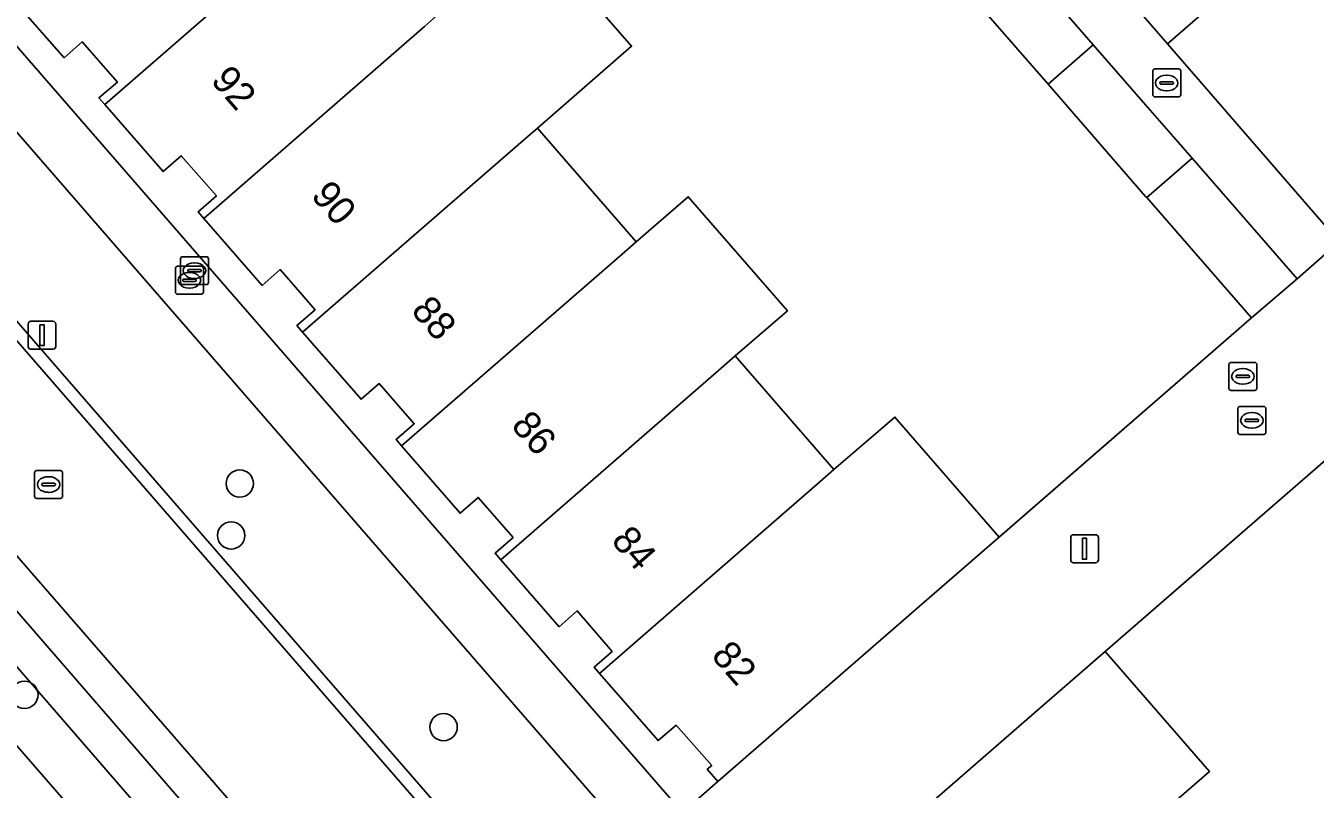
# Model space of a CAD drawing. Extents: x 155887 to 156869, y 383880 to 384678.
# Drawn here: x 156459.92 to 156506.07, y 384116.44 to 384143.78 of the extents above; entities that cross this region are included whole.
import ezdxf

# ---------------------------------------------------------------- set-up
doc = ezdxf.new("R2010")
doc.units = 0
for name, color, linetype in [('IMGEO_Berm_groen', 7, 'Continuous'), ('IMGEO_Boom', 7, 'Continuous'), ('IMGEO_Brandkraan', 7, 'Continuous'), ('IMGEO_Erf', 7, 'Continuous'), ('IMGEO_Greppel_droge_sloot', 7, 'Continuous'), ('IMGEO_Kolk', 7, 'Continuous'), ('IMGEO_Lichtmast', 7, 'Continuous'), ('IMGEO_Muur', 7, 'Continuous'), ('IMGEO_OVBaan_gesloten', 7, 'Continuous'), ('IMGEO_Pand', 7, 'Continuous'), ('IMGEO_Pand_nummerreeks', 7, 'Continuous'), ('IMGEO_Parkeervlak_open', 7, 'Continuous'), ('IMGEO_Rijbaan_lokaal_gesloten', 7, 'Continuous'), ('IMGEO_Rijbaan_lokaal_open', 7, 'Continuous'), ('IMGEO_Rioolput', 7, 'Continuous'), ('IMGEO_Voetpad_open', 7, 'Continuous')]:
    doc.layers.add(name, color=color, linetype=linetype)

msp = doc.modelspace()

# ---------------------------------------------------------------- linework, layer by layer
at = {"layer": 'IMGEO_Berm_groen'}
for points in [[(156520.535, 384054.614), (156504.298, 384073.374), (156500, 384078.319), (156478.069, 384103.539), (156435.386, 384152.651), (156395.779, 384198.307), (156392.544, 384201.972), (156392.213, 384201.678), (156391.898, 384201.399), (156389.213, 384199.015), (156500, 384071.498), (156517.145, 384051.764)], [(156518.628, 384053.007), (156500, 384074.342), (156481.572, 384095.447), (156445.697, 384136.86), (156396.295, 384193.376), (156399.832, 384191.076), (156406.998, 384183.444), (156446.804, 384137.574), (156482.527, 384096.349), (156500, 384076.291), (156519.582, 384053.811)]]:
    msp.add_lwpolyline(points, dxfattribs=at)
at = {"layer": 'IMGEO_Boom'}
for centre in [(156467.574, 384127.385), (156467.265, 384125.531), (156459.865, 384119.824), (156474.872, 384118.668)]:
    msp.add_circle(centre, 0.489, dxfattribs=at)
at = {"layer": 'IMGEO_Brandkraan'}
for p, q in [((156465.454, 384134.583), (156465.454, 384135.435)), ((156465.529, 384135.509), (156466.381, 384135.509)), ((156465.942, 384135.289), (156465.967, 384135.289)), ((156466.455, 384135.435), (156466.455, 384134.583)), ((156465.274, 384134.239), (156465.274, 384135.091)), ((156465.349, 384135.165), (156466.201, 384135.165)), ((156465.713, 384135.003), (156465.713, 384135.015)), ((156466.151, 384134.966), (156465.753, 384134.966)), ((156465.756, 384135.052), (156466.154, 384135.052)), ((156465.762, 384134.945), (156465.787, 384134.945)), ((156466.197, 384135.015), (156466.197, 384135.003)), ((156466.275, 384135.091), (156466.275, 384134.239)), ((156466.381, 384134.509), (156465.529, 384134.509)), ((156465.533, 384134.659), (156465.533, 384134.671)), ((156465.971, 384134.622), (156465.573, 384134.622)), ((156465.576, 384134.708), (156465.974, 384134.708)), ((156465.785, 384134.385), (156465.76, 384134.385)), ((156465.965, 384134.729), (156465.94, 384134.729)), ((156466.017, 384134.671), (156466.017, 384134.659)), ((156466.201, 384134.165), (156465.349, 384134.165))]:
    msp.add_line(p, q, dxfattribs=at)
for points in [[(156465.454, 384134.583), (156465.454, 384135.435)], [(156465.529, 384135.509), (156466.381, 384135.509)], [(156466.455, 384135.435), (156466.455, 384134.583)], [(156465.274, 384134.239), (156465.274, 384135.091)], [(156465.349, 384135.165), (156466.201, 384135.165)], [(156466.275, 384135.091), (156466.275, 384134.239)], [(156466.381, 384134.509), (156465.529, 384134.509)], [(156466.201, 384134.165), (156465.349, 384134.165)]]:
    msp.add_lwpolyline(points, dxfattribs=at)
for centre, radius, start, end in [((156465.531, 384135.433), 0.0765, 91.552, 178.448), ((156465.531, 384135.433), 0.0765, 91.552, 178.448), ((156466.379, 384135.433), 0.0765, 1.552, 88.448), ((156466.379, 384135.433), 0.0765, 1.552, 88.448), ((156465.351, 384135.089), 0.0765, 91.552, 178.448), ((156465.351, 384135.089), 0.0765, 91.552, 178.448), ((156465.753, 384135.012), 0.0403, 85.8775, 175.7526), ((156465.75, 384135.002), 0.0366, 178.938, 274.7102), ((156466.154, 384135.009), 0.043, 264.8664, 352.4533), ((156466.158, 384135.014), 0.0386, 1.7309, 96.639), ((156466.199, 384135.089), 0.0765, 1.552, 88.448), ((156466.199, 384135.089), 0.0765, 1.552, 88.448), ((156465.531, 384134.585), 0.0765, 181.552, 268.448), ((156465.531, 384134.585), 0.0765, 181.552, 268.448), ((156465.573, 384134.668), 0.0403, 85.8775, 175.7526), ((156465.57, 384134.658), 0.0366, 178.938, 274.7102), ((156465.974, 384134.665), 0.043, 264.8664, 352.4533), ((156465.978, 384134.67), 0.0386, 1.7309, 96.639), ((156466.379, 384134.585), 0.0765, 271.552, 358.448), ((156466.379, 384134.585), 0.0765, 271.552, 358.448), ((156465.351, 384134.241), 0.0765, 181.552, 268.448), ((156465.351, 384134.241), 0.0765, 181.552, 268.448), ((156466.199, 384134.241), 0.0765, 271.552, 358.448), ((156466.199, 384134.241), 0.0765, 271.552, 358.448)]:
    msp.add_arc(centre, radius, start, end, dxfattribs=at)
for centre, major_axis, ratio, start_param, end_param in [((156465.941, 384135.009), (-0.387, 0.002), 0.722429, 4.712389, 7.853982), ((156465.966, 384135.009), (-0.39, 0.002), 0.717154, 1.570796, 4.712389), ((156465.761, 384134.665), (-0.387, 0.002), 0.722429, 4.712389, 7.853982), ((156465.786, 384134.665), (-0.39, 0.002), 0.717154, 1.570796, 4.712389)]:
    msp.add_ellipse(centre, major_axis=major_axis, ratio=ratio, start_param=start_param, end_param=end_param, dxfattribs=at)
at = {"layer": 'IMGEO_Erf'}
for points in [[(156447.623, 384156.834), (156483.427, 384115.614), (156484.683, 384116.72), (156484.308, 384117.159), (156484.468, 384117.295), (156483.201, 384118.73), (156482.547, 384118.183), (156480.45, 384120.589), (156480.257, 384120.81), (156480.906, 384121.375), (156479.656, 384122.826), (156479.008, 384122.26), (156476.917, 384124.656), (156476.713, 384124.89), (156477.361, 384125.456), (156476.11, 384126.89), (156475.461, 384126.326), (156473.369, 384128.736), (156473.17, 384128.966), (156473.819, 384129.53), (156472.567, 384130.968), (156471.918, 384130.403), (156469.826, 384132.807), (156469.621, 384133.043), (156470.27, 384133.607), (156469.025, 384135.047), (156468.377, 384134.482), (156466.286, 384136.882), (156466.083, 384137.115), (156466.738, 384137.686), (156465.481, 384139.124), (156464.833, 384138.559), (156462.744, 384140.954), (156462.534, 384141.194), (156463.199, 384141.759), (156461.94, 384143.198), (156461.292, 384142.633), (156459.196, 384145.034)], [(156478.058, 384147.119), (156481.599, 384143.047), (156478.23, 384140.116), (156481.768, 384136.039), (156483.627, 384137.657), (156487.176, 384133.576), (156485.312, 384131.955), (156488.844, 384127.885), (156490.676, 384129.465), (156491.026, 384129.767), (156494.76, 384125.465), (156503.787, 384133.316), (156500.039, 384137.624), (156500, 384137.669), (156496.505, 384141.686), (156492.954, 384145.767)], [(156500, 384144.033), (156500.779, 384143.137), (156504.594, 384146.446)], [(156507.439, 384129.09), (156498.546, 384121.378), (156502.29, 384117.077), (156499.486, 384114.64), (156500, 384114.048), (156503.026, 384110.564), (156506.565, 384106.489)]]:
    msp.add_lwpolyline(points, dxfattribs=at)
at = {"layer": 'IMGEO_Greppel_droge_sloot'}
msp.add_lwpolyline([(156519.582, 384053.811), (156500, 384076.291), (156482.527, 384096.349), (156446.804, 384137.574), (156406.998, 384183.444), (156399.832, 384191.076), (156396.295, 384193.376), (156445.697, 384136.86), (156481.572, 384095.447), (156500, 384074.342), (156518.628, 384053.007)], close=True, dxfattribs=at)
at = {"layer": 'IMGEO_Kolk'}
for p, q in [((156500.253, 384141.304), (156500.253, 384142.156)), ((156500.328, 384142.23), (156501.18, 384142.23)), ((156501.254, 384142.156), (156501.254, 384141.304)), ((156500.512, 384141.724), (156500.512, 384141.736)), ((156500.95, 384141.687), (156500.552, 384141.687)), ((156500.555, 384141.773), (156500.953, 384141.773)), ((156500.741, 384142.01), (156500.766, 384142.01)), ((156500.996, 384141.736), (156500.996, 384141.724)), ((156501.18, 384141.23), (156500.328, 384141.23)), ((156500.764, 384141.45), (156500.739, 384141.45)), ((156503.376, 384130.148), (156504.228, 384130.148)), ((156503.301, 384129.222), (156503.301, 384130.074)), ((156503.603, 384129.691), (156504.001, 384129.691)), ((156503.789, 384129.928), (156503.814, 384129.928)), ((156504.302, 384130.074), (156504.302, 384129.222)), ((156503.56, 384129.642), (156503.56, 384129.654)), ((156503.998, 384129.605), (156503.6, 384129.605)), ((156503.812, 384129.368), (156503.787, 384129.368)), ((156504.044, 384129.654), (156504.044, 384129.642)), ((156504.228, 384129.148), (156503.376, 384129.148))]:
    msp.add_line(p, q, dxfattribs=at)
for points in [[(156500.253, 384141.304), (156500.253, 384142.156)], [(156500.328, 384142.23), (156501.18, 384142.23)], [(156501.254, 384142.156), (156501.254, 384141.304)], [(156501.18, 384141.23), (156500.328, 384141.23)], [(156503.376, 384130.148), (156504.228, 384130.148)], [(156503.301, 384129.222), (156503.301, 384130.074)], [(156504.302, 384130.074), (156504.302, 384129.222)], [(156504.228, 384129.148), (156503.376, 384129.148)]]:
    msp.add_lwpolyline(points, dxfattribs=at)
for centre, radius, start, end in [((156500.33, 384142.154), 0.0765, 91.552, 178.448), ((156500.33, 384142.154), 0.0765, 91.552, 178.448), ((156501.178, 384142.154), 0.0765, 1.552, 88.448), ((156501.178, 384142.154), 0.0765, 1.552, 88.448), ((156500.552, 384141.733), 0.0403, 85.8775, 175.7526), ((156500.549, 384141.723), 0.0366, 178.938, 274.7102), ((156500.953, 384141.73), 0.043, 264.8664, 352.4533), ((156500.957, 384141.735), 0.0386, 1.7309, 96.639), ((156500.33, 384141.306), 0.0765, 181.552, 268.448), ((156500.33, 384141.306), 0.0765, 181.552, 268.448), ((156501.178, 384141.306), 0.0765, 271.552, 358.448), ((156501.178, 384141.306), 0.0765, 271.552, 358.448), ((156503.378, 384130.072), 0.0765, 91.552, 178.448), ((156503.378, 384130.072), 0.0765, 91.552, 178.448), ((156504.226, 384130.072), 0.0765, 1.552, 88.448), ((156504.226, 384130.072), 0.0765, 1.552, 88.448), ((156503.6, 384129.651), 0.0403, 85.8775, 175.7526), ((156504.005, 384129.653), 0.0386, 1.7309, 96.639), ((156503.378, 384129.224), 0.0765, 181.552, 268.448), ((156503.378, 384129.224), 0.0765, 181.552, 268.448), ((156503.597, 384129.641), 0.0366, 178.938, 274.7102), ((156504.001, 384129.648), 0.043, 264.8664, 352.4533), ((156504.226, 384129.224), 0.0765, 271.552, 358.448), ((156504.226, 384129.224), 0.0765, 271.552, 358.448)]:
    msp.add_arc(centre, radius, start, end, dxfattribs=at)
for centre, major_axis, ratio, start_param, end_param in [((156500.74, 384141.73), (-0.387, 0.002), 0.722429, 4.712389, 7.853982), ((156500.765, 384141.73), (-0.39, 0.002), 0.717154, 1.570796, 4.712389), ((156503.788, 384129.648), (-0.387, 0.002), 0.722429, 4.712389, 7.853982), ((156503.813, 384129.648), (-0.39, 0.002), 0.717154, 1.570796, 4.712389)]:
    msp.add_ellipse(centre, major_axis=major_axis, ratio=ratio, start_param=start_param, end_param=end_param, dxfattribs=at)
at = {"layer": 'IMGEO_Lichtmast'}
for p, q in [((156460, 384132.299), (156460, 384133.099)), ((156460, 384133.099), (156460, 384132.299)), ((156460.1, 384133.199), (156460.89, 384133.199)), ((156460.89, 384133.199), (156460.1, 384133.199)), ((156460.99, 384133.099), (156460.99, 384132.299)), ((156460.99, 384132.299), (156460.99, 384133.099)), ((156460.89, 384132.199), (156460.1, 384132.199)), ((156460.1, 384132.199), (156460.89, 384132.199)), ((156497.418, 384125.553), (156498.208, 384125.553)), ((156498.208, 384125.553), (156497.418, 384125.553)), ((156497.318, 384124.653), (156497.318, 384125.453)), ((156497.318, 384125.453), (156497.318, 384124.653)), ((156498.308, 384125.453), (156498.308, 384124.653)), ((156498.308, 384124.653), (156498.308, 384125.453)), ((156498.208, 384124.553), (156497.418, 384124.553)), ((156497.418, 384124.553), (156498.208, 384124.553))]:
    msp.add_line(p, q, dxfattribs=at)
for points in [[(156460.42, 384133.074), (156460.57, 384133.074), (156460.57, 384132.324), (156460.42, 384132.324), (156460.42, 384133.074)], [(156497.738, 384125.428), (156497.888, 384125.428), (156497.888, 384124.678), (156497.738, 384124.678), (156497.738, 384125.428)]]:
    msp.add_lwpolyline(points, dxfattribs=at)
for centre, start, end in [((156460.1, 384133.099), 90, 180), ((156460.1, 384133.099), 90, 180), ((156460.89, 384133.099), 0, 90), ((156460.89, 384133.099), 360, 90), ((156460.1, 384132.299), 180, 270), ((156460.1, 384132.299), 180, 270), ((156460.89, 384132.299), 270, 0), ((156460.89, 384132.299), 270, 0), ((156497.418, 384125.453), 90, 180), ((156497.418, 384125.453), 90, 180), ((156498.208, 384125.453), 0, 90), ((156498.208, 384125.453), 360, 90), ((156497.418, 384124.653), 180, 270), ((156497.418, 384124.653), 180, 270), ((156498.208, 384124.653), 270, 0), ((156498.208, 384124.653), 270, 0)]:
    msp.add_arc(centre, 0.1, start, end, dxfattribs=at)
at = {"layer": 'IMGEO_Muur'}
for points in [[(156494.41, 384125.163), (156503.787, 384133.316)], [(156495.749, 384118.943), (156507.439, 384129.09)]]:
    msp.add_lwpolyline(points, dxfattribs=at)
at = {"layer": 'IMGEO_OVBaan_gesloten'}
msp.add_lwpolyline([(156517.145, 384051.764), (156500, 384071.498), (156389.213, 384199.015), (156388.245, 384200.13), (156387.576, 384200.899), (156382.519, 384196.58), (156383.118, 384195.909), (156383.97, 384194.921), (156384.072, 384194.803), (156383.943, 384194.699), (156384.885, 384193.654), (156385.683, 384192.735), (156404.132, 384171.551), (156406.911, 384168.313), (156407.083, 384168.169), (156407.746, 384167.396), (156407.842, 384167.479), (156410.66, 384164.227), (156441.975, 384128.147), (156500, 384061.368), (156513.218, 384046.155)], dxfattribs=at)
at = {"layer": 'IMGEO_Pand'}
for points in [[(156471.08, 384148.209), (156467.537, 384152.29), (156467.101, 384151.91), (156459.196, 384145.034), (156461.292, 384142.633), (156461.94, 384143.198), (156463.199, 384141.759), (156462.534, 384141.194), (156462.744, 384140.954), (156470.643, 384147.829)], [(156503.731, 384152.702), (156501.128, 384150.443), (156504.594, 384146.446), (156500.779, 384143.137), (156506.931, 384136.042), (156507.318, 384135.596), (156507.559, 384135.806), (156507.342, 384136.055), (156506.563, 384136.949), (156510.999, 384140.816), (156511.793, 384139.906), (156511.484, 384139.638), (156511.694, 384139.397), (156513.744, 384141.181)], [(156474.621, 384144.13), (156471.08, 384148.209), (156470.643, 384147.829), (156462.744, 384140.954), (156464.833, 384138.559), (156465.481, 384139.124), (156466.738, 384137.686), (156466.083, 384137.115), (156466.286, 384136.882), (156474.184, 384143.75)], [(156478.23, 384140.116), (156481.599, 384143.047), (156478.058, 384147.119), (156474.621, 384144.13), (156474.184, 384143.75), (156466.286, 384136.882), (156468.377, 384134.482), (156469.025, 384135.047), (156470.27, 384133.607), (156469.621, 384133.043), (156469.826, 384132.807), (156477.721, 384139.674)], [(156496.505, 384141.686), (156498.127, 384143.096), (156494.576, 384147.178), (156492.954, 384145.767)], [(156501.661, 384139.035), (156500, 384140.944), (156498.127, 384143.096), (156496.505, 384141.686), (156500, 384137.669), (156500.039, 384137.624)], [(156481.768, 384136.039), (156478.23, 384140.116), (156477.721, 384139.674), (156469.826, 384132.807), (156471.918, 384130.403), (156472.567, 384130.968), (156473.819, 384129.53), (156473.17, 384128.966), (156473.369, 384128.736), (156481.259, 384135.597)], [(156501.661, 384139.035), (156500.039, 384137.624), (156503.787, 384133.316), (156505.418, 384134.717)], [(156485.312, 384131.955), (156487.176, 384133.576), (156483.627, 384137.657), (156481.768, 384136.039), (156481.259, 384135.597), (156473.369, 384128.736), (156475.461, 384126.326), (156476.11, 384126.89), (156477.361, 384125.456), (156476.713, 384124.89), (156476.917, 384124.656), (156484.804, 384131.513)], [(156488.844, 384127.885), (156485.312, 384131.955), (156484.804, 384131.513), (156476.917, 384124.656), (156479.008, 384122.26), (156479.656, 384122.826), (156480.906, 384121.375), (156480.257, 384120.81), (156480.45, 384120.589), (156488.334, 384127.445)], [(156494.76, 384125.465), (156491.026, 384129.767), (156490.676, 384129.465), (156488.844, 384127.885), (156488.334, 384127.445), (156480.45, 384120.589), (156482.547, 384118.183), (156483.201, 384118.73), (156484.468, 384117.295), (156484.308, 384117.159), (156484.683, 384116.72), (156492.068, 384123.143), (156494.41, 384125.163)], [(156499.486, 384114.64), (156502.29, 384117.077), (156498.546, 384121.378), (156495.749, 384118.943), (156487.849, 384112.066), (156490.131, 384109.441), (156490.78, 384110.005), (156492.034, 384108.551), (156491.384, 384107.998), (156491.582, 384107.771)]]:
    msp.add_lwpolyline(points, close=True, dxfattribs=at)
at = {"layer": 'IMGEO_Parkeervlak_open'}
msp.add_lwpolyline([(156477.224, 384112.901), (156478.974, 384114.375), (156480.274, 384112.885), (156481.885, 384114.292), (156446.092, 384155.517), (156444.501, 384154.132), (156445.796, 384152.598), (156444.047, 384151.107)], close=True, dxfattribs=at)
at = {"layer": 'IMGEO_Rijbaan_lokaal_gesloten'}
msp.add_lwpolyline([(156516.29, 384067.237), (156500, 384085.986), (156483.127, 384105.407), (156481.951, 384106.723), (156476.876, 384112.6), (156443.7, 384150.805), (156437.383, 384158.067), (156399.273, 384201.968), (156396.428, 384205.193), (156395.961, 384205.703), (156395.847, 384205.822), (156395.745, 384205.951), (156395.653, 384206.088), (156395.631, 384206.125), (156391.587, 384203.129), (156392.544, 384201.972), (156395.779, 384198.307), (156435.386, 384152.651), (156478.069, 384103.539), (156500, 384078.319), (156504.298, 384073.374), (156520.535, 384054.614)], dxfattribs=at)
at = {"layer": 'IMGEO_Rijbaan_lokaal_open'}
for points in [[(156395.506, 384206.265), (156395.623, 384206.134), (156395.631, 384206.125), (156395.653, 384206.088), (156395.745, 384205.951), (156395.847, 384205.822), (156395.961, 384205.703), (156396.428, 384205.193), (156399.273, 384201.968), (156437.383, 384158.067), (156443.7, 384150.805), (156476.876, 384112.6), (156481.951, 384106.723), (156483.127, 384105.407), (156500, 384085.986), (156516.29, 384067.237), (156517.607, 384065.738), (156518.453, 384064.739), (156519.101, 384063.991), (156519.163, 384063.918), (156519.227, 384063.847), (156519.291, 384063.776)], [(156519.449, 384064.292), (156518.802, 384065.038), (156517.955, 384066.038), (156516.636, 384067.54), (156500, 384086.688), (156483.472, 384105.711), (156482.297, 384107.027), (156477.224, 384112.901), (156444.047, 384151.107), (156437.73, 384158.369), (156399.619, 384202.271)]]:
    msp.add_lwpolyline(points, dxfattribs=at)
at = {"layer": 'IMGEO_Rioolput'}
for p, q in [((156502.979, 384130.796), (156502.979, 384131.648)), ((156503.054, 384131.722), (156503.906, 384131.722)), ((156503.98, 384131.648), (156503.98, 384130.796)), ((156503.238, 384131.216), (156503.238, 384131.228)), ((156503.676, 384131.179), (156503.278, 384131.179)), ((156503.281, 384131.265), (156503.679, 384131.265)), ((156503.467, 384131.502), (156503.492, 384131.502)), ((156503.722, 384131.228), (156503.722, 384131.216)), ((156503.906, 384130.722), (156503.054, 384130.722)), ((156503.49, 384130.942), (156503.465, 384130.942)), ((156460.308, 384127.852), (156461.16, 384127.852)), ((156460.233, 384126.926), (156460.233, 384127.778)), ((156460.492, 384127.346), (156460.492, 384127.358)), ((156460.535, 384127.395), (156460.933, 384127.395)), ((156460.721, 384127.632), (156460.746, 384127.632)), ((156460.976, 384127.358), (156460.976, 384127.346)), ((156461.234, 384127.778), (156461.234, 384126.926)), ((156460.93, 384127.309), (156460.532, 384127.309)), ((156460.744, 384127.072), (156460.719, 384127.072)), ((156461.16, 384126.852), (156460.308, 384126.852))]:
    msp.add_line(p, q, dxfattribs=at)
for points in [[(156502.979, 384130.796), (156502.979, 384131.648)], [(156503.054, 384131.722), (156503.906, 384131.722)], [(156503.98, 384131.648), (156503.98, 384130.796)], [(156503.906, 384130.722), (156503.054, 384130.722)], [(156460.308, 384127.852), (156461.16, 384127.852)], [(156460.233, 384126.926), (156460.233, 384127.778)], [(156461.234, 384127.778), (156461.234, 384126.926)], [(156461.16, 384126.852), (156460.308, 384126.852)]]:
    msp.add_lwpolyline(points, dxfattribs=at)
for centre, radius, start, end in [((156503.056, 384131.646), 0.0765, 91.552, 178.448), ((156503.056, 384131.646), 0.0765, 91.552, 178.448), ((156503.904, 384131.646), 0.0765, 1.552, 88.448), ((156503.904, 384131.646), 0.0765, 1.552, 88.448), ((156503.278, 384131.225), 0.0403, 85.8775, 175.7526), ((156503.275, 384131.215), 0.0366, 178.938, 274.7102), ((156503.679, 384131.222), 0.043, 264.8664, 352.4533), ((156503.683, 384131.227), 0.0386, 1.7309, 96.639), ((156503.056, 384130.798), 0.0765, 181.552, 268.448), ((156503.056, 384130.798), 0.0765, 181.552, 268.448), ((156503.904, 384130.798), 0.0765, 271.552, 358.448), ((156503.904, 384130.798), 0.0765, 271.552, 358.448), ((156460.31, 384127.776), 0.0765, 91.552, 178.448), ((156460.31, 384127.776), 0.0765, 91.552, 178.448), ((156461.158, 384127.776), 0.0765, 1.552, 88.448), ((156461.158, 384127.776), 0.0765, 1.552, 88.448), ((156460.532, 384127.355), 0.0403, 85.8775, 175.7526), ((156460.937, 384127.357), 0.0386, 1.7309, 96.639), ((156460.31, 384126.928), 0.0765, 181.552, 268.448), ((156460.31, 384126.928), 0.0765, 181.552, 268.448), ((156460.529, 384127.345), 0.0366, 178.938, 274.7102), ((156460.933, 384127.352), 0.043, 264.8664, 352.4533), ((156461.158, 384126.928), 0.0765, 271.552, 358.448), ((156461.158, 384126.928), 0.0765, 271.552, 358.448)]:
    msp.add_arc(centre, radius, start, end, dxfattribs=at)
for centre, major_axis, ratio, start_param, end_param in [((156503.466, 384131.222), (-0.387, 0.002), 0.722429, 4.712389, 7.853982), ((156503.491, 384131.222), (-0.39, 0.002), 0.717154, 1.570796, 4.712389), ((156460.72, 384127.352), (-0.387, 0.002), 0.722429, 4.712389, 7.853982), ((156460.745, 384127.352), (-0.39, 0.002), 0.717154, 1.570796, 4.712389)]:
    msp.add_ellipse(centre, major_axis=major_axis, ratio=ratio, start_param=start_param, end_param=end_param, dxfattribs=at)
at = {"layer": 'IMGEO_Voetpad_open'}
for points in [[(156500.779, 384143.137), (156500, 384144.033), (156479.76, 384167.325), (156473.227, 384174.856), (156471.67, 384173.505), (156473.31, 384171.62), (156476.853, 384167.547), (156480.397, 384163.475), (156483.94, 384159.402), (156487.491, 384155.321), (156491.032, 384151.252), (156494.576, 384147.178), (156498.127, 384143.096), (156500, 384140.944), (156501.661, 384139.035), (156505.418, 384134.717), (156506.931, 384136.042)], [(156447.623, 384156.834), (156446.092, 384155.517), (156481.885, 384114.292), (156483.427, 384115.614)], [(156507.439, 384129.09), (156509.058, 384130.495), (156510.697, 384131.927), (156508.749, 384134.216), (156507.318, 384135.596), (156506.931, 384136.042), (156505.418, 384134.717), (156503.787, 384133.316), (156494.76, 384125.465), (156494.41, 384125.163), (156492.068, 384123.143), (156484.683, 384116.72), (156483.427, 384115.614), (156487.105, 384111.402), (156487.849, 384112.066), (156495.749, 384118.943), (156498.546, 384121.378)]]:
    msp.add_lwpolyline(points, close=True, dxfattribs=at)

# ---------------------------------------------------------------- texts
at = {"layer": 'IMGEO_Pand_nummerreeks'}
for s, p in [('92', (156466.505, 384141.799)), ('90', (156470.091, 384137.675)), ('88', (156473.673, 384133.556)), ('86', (156477.253, 384129.44)), ('84', (156480.835, 384125.321)), ('82', (156484.416, 384121.204))]:
    msp.add_text(s, height=1, rotation=311.0121, dxfattribs=at).set_placement(p)

doc.saveas('drawing.dxf')
